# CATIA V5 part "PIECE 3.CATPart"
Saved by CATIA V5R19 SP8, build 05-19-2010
Part number: PIECE 3
Bounding box of the stored display mesh (mm): x -11 to 0, y -12.81 to 14.47, z 0.541 to 46.913
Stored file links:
  C:\Users\ThinkMotion\Desktop\EU_thinkMotion\iao\IAO_MMS_Groupe3\jbuffard\jbuffard\PIECE 3.CATPart
  C:\Users\ThinkMotion\Desktop\EU_thinkMotion\iao\IAO_MMS_Groupe3\jbuffard\jbuffard\Mecanisme a coulisse a quatre elements de la griffe d'une camera.CATProduct
  C:\Users\ThinkMotion\Desktop\EU_thinkMotion\iao\IAO_MMS_Groupe3\jbuffard\jbuffard\Squelette PIECE 3.CATPart
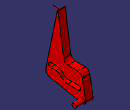
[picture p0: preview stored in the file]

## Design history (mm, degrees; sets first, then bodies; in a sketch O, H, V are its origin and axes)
External parameters (linked from other documents)
  `External.Diametre doigt/rainures` = 0.0015
Set1
  Plane1: linked copy from another document
  Point1: linked copy from another document
  Point2: linked copy from another document
  DatumCurve1: linked copy from another document
  Point3: linked copy from another document
  Plane2 to Plane4: linked copy from another document
Body1 (main body)
  Sketch1 on Plane1, origin (-6, 0, 0), H (0, 1, 0), V (0, 0, 1)
    arc A1 centre (-9.5, 12.5) radius 1.5 from (-9.5, 14) to (-9.5, 11) ccw
    point P1 (-9.5, 12.5)
    arc A2 centre (9.5, 8.5) radius 1.5 from (9.5, 7) to (9.5, 10) ccw
    point P2 (9.5, 8.5)
    reference projected point E1 (9.5, 8.5) from Point1
    reference projected point E2 (-9.5, 12.5) from Point2
    line L1 (-9.5, 14) -> (-5.6664, 14)
    line L2 (9.5, 7) -> (2.0616, 7)
    line L3 (-9.5, 11) -> (-5.6664, 11)
    line L4 (9.5, 10) -> (2.0616, 10)
    line L5 (-1.4237, 12.2426) -> (-0.0598, 10.8787)
    reference projected line E3 (-2.4844, 11.182) -> (-1.1204, 9.818) from edge of DatumCurve1
    reference projected line E4 (-2.4844, 11.182) -> (-1.1204, 9.818) from edge of DatumCurve1
    line L6 (-3.545, 10.1213) -> (-2.1811, 8.7574)
    reference projected line E5 (-2.4844, 11.182) -> (-1.1204, 9.818) from edge of DatumCurve1
    arc A3 centre (-5.6664, 8) radius 3 from (-5.6664, 11) to (-3.545, 10.1213) cw
    arc A4 centre (-5.6664, 8) radius 6 from (-5.6664, 14) to (-1.4237, 12.2426) cw
    arc A5 centre (2.0616, 13) radius 6 from (-2.1811, 8.7574) to (2.0616, 7) ccw
    arc A6 centre (2.0616, 13) radius 3 from (-0.0598, 10.8787) to (2.0616, 10) ccw
    point P19 (-4.6128, 47.8639)
    line L7 (-4.6128, 47.8639) -> (-12.8103, 8.7256)
    point P20 (-13.4278, 5.7772)
    line L8 (-10.4769, 5.1718) -> (12.0981, 0.5408)
    point P21 (14.9806, -0.0505)
    line L9 (14.4696, 2.8473) -> (12.2052, 15.6894)
    point P22 (11.7681, 18.1684)
    line L10 (9.2508, 18.1684) -> (2.2508, 18.1684)
    point P23 (-0.3492, 18.1684)
    line L11 (-0.7188, 20.7421) -> (-4.6128, 47.8639)
    arc A7 centre (-9.874, 8.1106) radius 3 from (-12.8103, 8.7256) to (-10.4769, 5.1718) ccw
    arc A8 centre (12.5, 2.5) radius 2 from (12.0981, 0.5408) to (14.4696, 2.8473) ccw
    point P29 (12.5, 2.5)
    arc A9 centre (9.2508, 15.1684) radius 3 from (9.2508, 18.1684) to (12.2052, 15.6894) cw
    arc A10 centre (2.2508, 21.1684) radius 3 from (-0.7188, 20.7421) to (2.2508, 18.1684) ccw
    reference projected point E6 (12.5, 2.5) from Point3
    radius A2 = 1.5 {= `External.Diametre doigt/rainures`}
    radius A1 = 1.5 {= `External.Diametre doigt/rainures`}
    distance L5 E4 = 1.5 {= `External.Diametre doigt/rainures`}
    distance E5 L6 = 1.5 {= `External.Diametre doigt/rainures`}
    radius A3 = 3
    radius A4 = 6
    radius A5 = 6
    radius A6 = 3
    angle L7 L11 = 160
    angle L10 L9 = 100
    distance P19 P20 = 43
    distance P20 P21 = 29
    radius A7 = 3
    distance P21 P22 = 18.5
    radius A8 = 2
    radius A9 = 3
    distance P23 P19 = 30
    radius A10 = 3
    length L10 = 7
    coincidence: P2 E1, P1 E2, L7 P20, L8 P20, L8 P21, L9 P21, L10 P22, L9 P22, L11 P23, L10 P23, P29 E6
    horizontal: L1 H, L2 H, L3 H, L4 H, L10 H
    tangency: L2 A2, L1 A1, L3 A1, L4 A2, A3 L3, A3 L6, A4 L1, A4 L5, A5 L6, A5 L2, A6 L5, A6 L4, A7 L7, A7 L8, A8 L8, A8 L9, A9 L10, A9 L9, A10 L11, A10 L10
    parallelism: L5 E3
  Pad1: profile Sketch1, direction (-1, 0, 0), up to Plane2
  Sketch2 on Plane3, origin (-6, 0, 0), H (0, 1, 0), V (0, 0, 1)
    circle A1 centre (12.5, 2.5) radius 1.5
    point P1 (12.5, 2.5)
    reference projected point E1 (12.5, 2.5) from Point3
    radius A1 = 1.5
    coincidence: E1 P1
  Pad2: profile Sketch2, direction (1, 0, 0), up to yz-plane
  Sketch3 on Plane4, origin (-8.5, 0, 0), H (0, 1, 0), V (0, 0, 1)
    line L1 (-10.1216, 45.9526) -> (-5.0228, 45.9064)
    point P2 (-5.0228, 45.9064)
    line L2 (-5.0228, 45.9064) -> (-5.2278, 44.9276)
    line L3 (-5.2278, 44.9276) -> (-10.1216, 45.9526)
    reference intersected line E1 (-12.8103, 8.7256) -> (-4.6128, 47.8639) from face of Pad1 from Sketch1.L7
    reference projected line E2 (-4.6128, 47.8639) -> (-12.8103, 8.7256) from edge [face of Pad1 from Sketch1.L7 | start face of Pad1]
    reference intersected line E3 (-12.8103, 8.7256) -> (-4.6128, 47.8639) from face of Pad1 from Sketch1.L7
    reference projected point E4 (-4.6128, 47.8639) from edge [face of Pad1 from Sketch1.L11 | face of Pad1 from Sketch1.L7]
    length L2 = 1
    distance P2 E4 = 2
    length L3 = 5
    coincidence: L2 E1
    parallelism: L2 E2
    perpendicularity: L3 E3
  Shaft1: profile Sketch3, axis Sketch3.L3, angle 360
  Fillet1: radius 0.2, on edge [face of Pad1 from Sketch1.L11 | face of Pad1 from Sketch1.L7]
